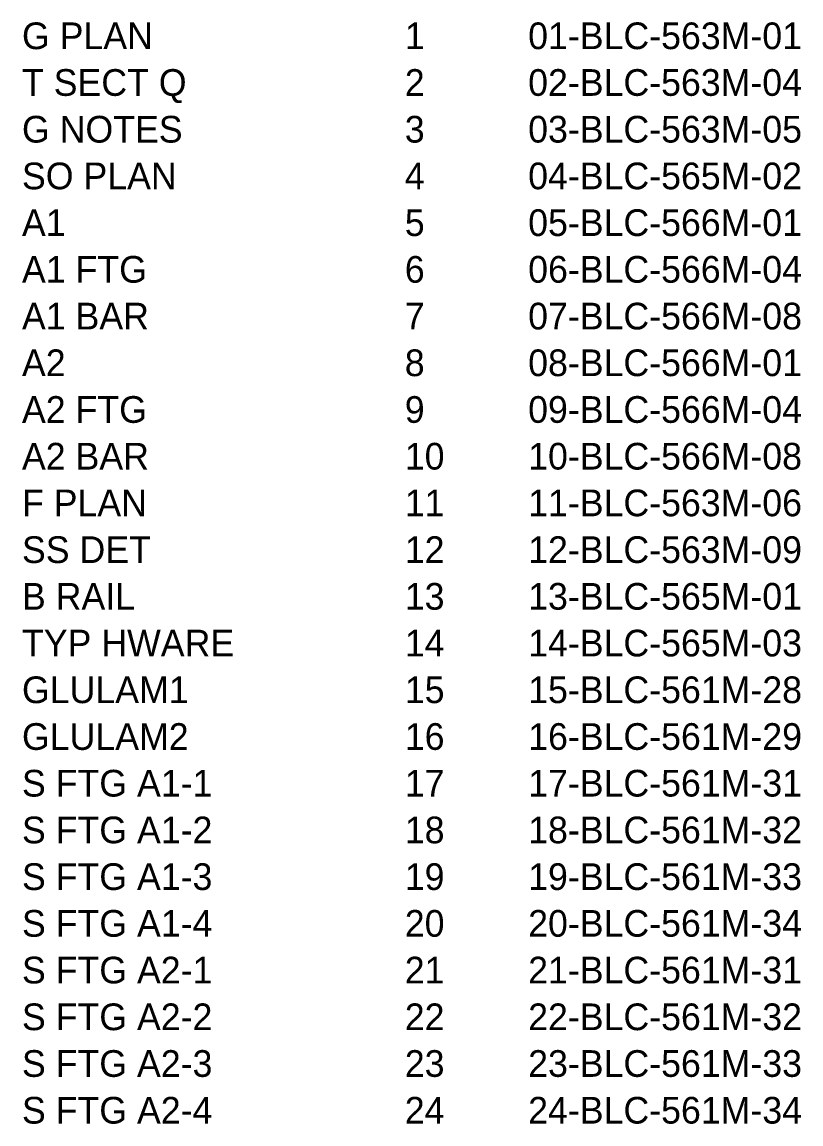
# Model space of a CAD drawing. Extents: x -762 to 6536, y -6882 to 0.
# Drawn here: x 136 to 2188, y -6861 to -3959 of the extents above; entities that cross this region are included whole.
import ezdxf

# ---------------------------------------------------------------- set-up
doc = ezdxf.new("R2010")
doc.units = 0
doc.layers.add('62', color=7, linetype='Continuous')

msp = doc.modelspace()

# ---------------------------------------------------------------- texts
at = {"layer": '62'}
for s, height, p in [('G PLAN', 70.31, (135.9, -4030.4)), ('1', 70.3, (1144.2, -4030.4)), ('01-BLC-563M-01', 70.313, (1469.1, -4030.4)), ('T SECT Q', 70.31, (135.9, -4153.4)), ('2', 70.3, (1144.2, -4153.4)), ('02-BLC-563M-04', 70.313, (1469.1, -4153.4)), ('G NOTES', 70.31, (135.9, -4276.5)), ('3', 70.3, (1144.2, -4276.5)), ('03-BLC-563M-05', 70.313, (1469.1, -4276.5)), ('SO PLAN', 70.31, (135.9, -4399.5)), ('4', 70.3, (1144.2, -4399.5)), ('04-BLC-565M-02', 70.313, (1469.1, -4399.5)), ('A1', 70.31, (135.9, -4522.6)), ('5', 70.3, (1144.2, -4522.6)), ('05-BLC-566M-01', 70.313, (1469.1, -4522.6)), ('A1 FTG', 70.31, (135.9, -4645.6)), ('6', 70.3, (1144.2, -4645.6)), ('06-BLC-566M-04', 70.313, (1469.1, -4645.6)), ('A1 BAR', 70.31, (135.9, -4768.7)), ('7', 70.3, (1144.2, -4768.7)), ('07-BLC-566M-08', 70.313, (1469.1, -4768.7)), ('A2', 70.31, (135.9, -4891.7)), ('8', 70.3, (1144.2, -4891.7)), ('08-BLC-566M-01', 70.313, (1469.1, -4891.7)), ('A2 FTG', 70.31, (135.9, -5014.7)), ('9', 70.3, (1144.2, -5014.7)), ('09-BLC-566M-04', 70.313, (1469.1, -5014.7)), ('A2 BAR', 70.31, (135.9, -5137.8)), ('10', 70.31, (1144.2, -5137.8)), ('10-BLC-566M-08', 70.313, (1469.1, -5137.8)), ('F PLAN', 70.31, (135.9, -5260.8)), ('11', 70.31, (1144.2, -5260.8)), ('11-BLC-563M-06', 70.313, (1469.1, -5260.8)), ('SS DET', 70.31, (135.9, -5383.9)), ('12', 70.31, (1144.2, -5383.9)), ('12-BLC-563M-09', 70.313, (1469.1, -5383.9)), ('B RAIL', 70.31, (135.9, -5506.9)), ('13', 70.31, (1144.2, -5506.9)), ('13-BLC-565M-01', 70.313, (1469.1, -5506.9)), ('TYP HWARE', 70.31, (135.9, -5630)), ('14', 70.31, (1144.2, -5630)), ('14-BLC-565M-03', 70.313, (1469.1, -5630)), ('GLULAM1', 70.31, (135.9, -5753)), ('15', 70.31, (1144.2, -5753)), ('15-BLC-561M-28', 70.313, (1469.1, -5753)), ('GLULAM2', 70.31, (135.9, -5876.1)), ('16', 70.31, (1144.2, -5876.1)), ('16-BLC-561M-29', 70.313, (1469.1, -5876.1)), ('S FTG A1-1', 70.31, (135.9, -5999.1)), ('17', 70.31, (1144.2, -5999.1)), ('17-BLC-561M-31', 70.313, (1469.1, -5999.1)), ('S FTG A1-2', 70.31, (135.9, -6122.2)), ('18', 70.31, (1144.2, -6122.2)), ('18-BLC-561M-32', 70.313, (1469.1, -6122.2)), ('S FTG A1-3', 70.31, (135.9, -6245.2)), ('19', 70.31, (1144.2, -6245.2)), ('19-BLC-561M-33', 70.313, (1469.1, -6245.2)), ('S FTG A1-4', 70.31, (135.9, -6368.3)), ('20', 70.31, (1144.2, -6368.3)), ('20-BLC-561M-34', 70.313, (1469.1, -6368.3)), ('S FTG A2-1', 70.31, (135.9, -6491.3)), ('21', 70.31, (1144.2, -6491.3)), ('21-BLC-561M-31', 70.313, (1469.1, -6491.3)), ('S FTG A2-2', 70.31, (135.9, -6614.4)), ('22', 70.31, (1144.2, -6614.4)), ('22-BLC-561M-32', 70.313, (1469.1, -6614.4)), ('S FTG A2-3', 70.31, (135.9, -6737.4)), ('23', 70.31, (1144.2, -6737.4)), ('23-BLC-561M-33', 70.313, (1469.1, -6737.4)), ('S FTG A2-4', 70.31, (135.9, -6860.5)), ('24', 70.31, (1144.2, -6860.5)), ('24-BLC-561M-34', 70.313, (1469.1, -6860.5))]:
    msp.add_text(s, height=height, dxfattribs=at).set_placement(p)

doc.saveas('drawing.dxf')
